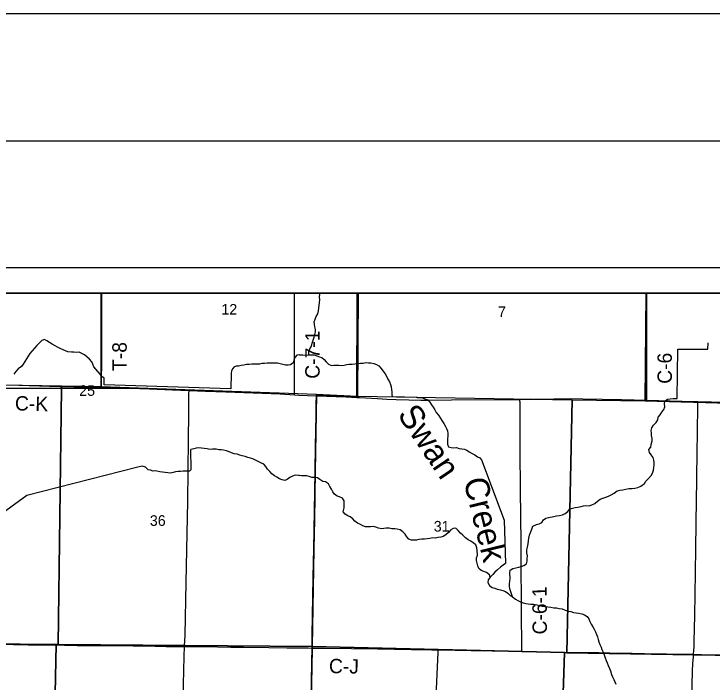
# Model space of a CAD drawing. Extents: x 0 to 42, y 0 to 22.
# Drawn here: x 5.107 to 7.86, y 19.367 to 22 of the extents above; entities that cross this region are included whole.
import ezdxf

# ---------------------------------------------------------------- set-up
doc = ezdxf.new("R2010")
doc.units = 0
for name, color, linetype in [('Default', 7, 'Continuous'), ('GM_X_County_Road', 7, 'Continuous'), ('GM_X_County_Road_Text', 7, 'Continuous'), ('GM_X_Interchange_Ramps', 7, 'Continuous'), ('GM_X_Minor_River', 7, 'Continuous'), ('GM_X_Minor_River_Text', 7, 'Continuous'), ('GM_X_Section', 7, 'Continuous'), ('GM_X_Section_Text', 7, 'Continuous'), ('GM_X_Township_Road', 7, 'Continuous'), ('GM_X_Township_Road_Text', 7, 'Continuous'), ('SH_Border', 7, 'Continuous'), ('SH_Cut_Line', 7, 'Continuous'), ('SH_Data', 7, 'Continuous')]:
    doc.layers.add(name, color=color, linetype=linetype)

msp = doc.modelspace()

# ---------------------------------------------------------------- linework, layer by layer
at = {"layer": 'Default'}
for points in [[(5.4509, 20.9), (4.4477, 20.9), (4.4454, 20.5483), (5.2948, 20.5335), (5.4509, 20.5312)], [(6.4644, 20.9), (5.4509, 20.9), (5.4509, 20.5312), (5.6345, 20.5244), (6.2999, 20.501), (6.462, 20.4934)], [(7.6, 20.9), (6.4644, 20.9), (6.462, 20.4934), (7.3083, 20.4793), (7.5963, 20.4744)], [(8.5893, 20.9), (7.6, 20.9), (7.5963, 20.4744), (8.3092, 20.4559), (8.5911, 20.4514)]]:
    msp.add_lwpolyline(points, close=True, dxfattribs=at)
at = {"layer": 'GM_X_County_Road'}
for points in [[(6.2135, 20.4987), (6.2136, 20.5048), (6.2138, 20.5141), (6.2138, 20.5638), (6.2132, 20.741), (6.2132, 20.7658), (6.2133, 20.8249), (6.2136, 20.9)], [(7.6021, 20.4775), (7.6021, 20.4852), (7.6026, 20.9)], [(5.0427, 20.5382), (5.1257, 20.5362), (5.2872, 20.5311), (5.3432, 20.5304), (5.3991, 20.5296), (5.4507, 20.5283)], [(5.4507, 20.5283), (5.483, 20.5275), (5.5638, 20.5245), (5.6414, 20.5217), (5.7315, 20.5182), (5.7972, 20.5158)], [(5.7796, 19.5062), (5.7797, 19.5073), (5.7821, 19.5508), (5.7866, 19.7591), (5.7903, 19.9519), (5.7924, 20.0793), (5.7935, 20.2006), (5.7951, 20.3219), (5.7962, 20.4245), (5.7971, 20.5022), (5.7972, 20.5158)], [(5.7972, 20.5158), (5.862, 20.5134), (5.9427, 20.51), (6.157, 20.5021), (6.2135, 20.4987)], [(6.2135, 20.4987), (6.2306, 20.4977), (6.3003, 20.4952)], [(6.2825, 19.5006), (6.2829, 19.5488), (6.287, 19.7788), (6.2917, 20.0054), (6.2961, 20.2943), (6.2983, 20.4186), (6.2993, 20.4621), (6.3003, 20.4952)], [(6.3003, 20.4952), (6.417, 20.4902), (6.4593, 20.4883)], [(6.4593, 20.4883), (6.4698, 20.4878), (6.5406, 20.4838), (6.5774, 20.4815), (6.6146, 20.48), (6.6643, 20.4784), (6.711, 20.4777), (6.7452, 20.4777), (6.8322, 20.4787), (7.0903, 20.4805), (7.1023, 20.4807)], [(7.1023, 20.4807), (7.1575, 20.4817), (7.2353, 20.4835), (7.3006, 20.4842), (7.3504, 20.4834), (7.5027, 20.48), (7.6021, 20.4775)], [(7.1102, 19.4873), (7.1101, 19.4976), (7.1088, 19.6466), (7.1087, 19.6682), (7.1088, 19.6736), (7.1071, 19.8343), (7.1066, 19.9152), (7.1048, 20.1238), (7.1037, 20.2794), (7.1033, 20.376), (7.1026, 20.4694), (7.1024, 20.4734), (7.1023, 20.4796), (7.1023, 20.4807)], [(7.6021, 20.4775), (7.6488, 20.4763), (7.7887, 20.4724), (7.8038, 20.472)], [(7.787, 19.4762), (7.7891, 19.5049), (7.79, 19.5267), (7.7917, 19.6294), (7.7942, 19.7973), (7.7956, 19.8938), (7.7985, 20.0866), (7.7997, 20.1581), (7.7997, 20.1706), (7.7999, 20.2017), (7.8006, 20.2421), (7.8012, 20.2763), (7.8019, 20.3447), (7.8037, 20.4629), (7.8038, 20.472)], [(7.8038, 20.472), (7.8571, 20.4705), (7.9317, 20.4681), (7.9752, 20.4667), (8.0436, 20.4648), (8.1741, 20.4605), (8.2425, 20.4581), (8.3077, 20.4565)], [(5.0163, 19.5159), (5.0451, 19.5156), (5.1633, 19.5136), (5.2068, 19.5132), (5.3063, 19.5118), (5.3561, 19.5112), (5.4338, 19.5102), (5.468, 19.51), (5.5768, 19.509), (5.6639, 19.5079), (5.7074, 19.5072), (5.7665, 19.5062), (5.7796, 19.5062)], [(5.7716, 19.1917), (5.7779, 19.4669), (5.7796, 19.5062)], [(5.7796, 19.5062), (5.7976, 19.506), (5.9095, 19.505), (5.9624, 19.5043), (6.0121, 19.5038), (6.1116, 19.5024), (6.1832, 19.5016), (6.2671, 19.5008), (6.2825, 19.5006)], [(6.2634, 18.4929), (6.266, 18.6228), (6.2765, 19.1383), (6.2768, 19.1534), (6.2825, 19.496), (6.2825, 19.5006)], [(6.2825, 19.5006), (6.2917, 19.5006), (6.3352, 19.5003), (6.5404, 19.497), (6.6741, 19.4945), (6.7549, 19.4934), (6.7804, 19.4929)], [(6.7429, 18.4872), (6.7432, 18.4982), (6.7458, 18.5945), (6.7537, 18.8835), (6.7565, 18.983), (6.76, 19.0605), (6.762, 19.1054), (6.7628, 19.1211), (6.7681, 19.2375), (6.7728, 19.34), (6.7796, 19.4828), (6.7799, 19.4859), (6.7804, 19.4929)], [(6.7804, 19.4929), (6.9103, 19.4906), (7.075, 19.4879), (7.1102, 19.4873)], [(7.1102, 19.4873), (7.1621, 19.4865), (7.3299, 19.4836), (7.4139, 19.4824), (7.4574, 19.4815), (7.5444, 19.4803), (7.5941, 19.4795), (7.7682, 19.4765), (7.787, 19.4762)], [(7.7638, 18.7981), (7.7647, 18.8288), (7.7663, 18.8628), (7.767, 18.8942), (7.7675, 18.9147), (7.7681, 18.9395), (7.7708, 19.0266), (7.7744, 19.148), (7.7744, 19.1508), (7.7749, 19.1634), (7.7787, 19.2813), (7.7797, 19.2999), (7.783, 19.4088), (7.7844, 19.4398), (7.7862, 19.4646), (7.787, 19.4762)], [(7.787, 19.4762), (7.8178, 19.4757), (7.9391, 19.4738), (8.1877, 19.4699), (8.2889, 19.4687)]]:
    msp.add_lwpolyline(points, dxfattribs=at)
at = {"layer": 'GM_X_Interchange_Ramps'}
for points in [[(6.2766, 19.154), (6.2823, 19.4965), (6.2823, 19.5012), (6.2827, 19.5494), (6.2868, 19.7794), (6.2915, 20.006), (6.2959, 20.2948), (6.298, 20.4191), (6.299, 20.4627), (6.3001, 20.4958), (6.4167, 20.4908), (6.459, 20.4888), (6.4601, 20.9), (2.1, 20.9)], [(8.9, 18.4589), (8.9, 20.9), (6.4601, 20.9), (6.459, 20.4888), (6.4167, 20.4908), (6.3001, 20.4958), (6.299, 20.4627), (6.298, 20.4191), (6.2959, 20.2948), (6.2915, 20.006), (6.2868, 19.7794), (6.2827, 19.5494), (6.2823, 19.5012), (6.2823, 19.4965), (6.2766, 19.154)]]:
    msp.add_lwpolyline(points, dxfattribs=at)
at = {"layer": 'GM_X_Minor_River'}
for points in [[(6.2694, 20.6563), (6.2696, 20.6696), (6.274, 20.6801), (6.2799, 20.6902), (6.2828, 20.702), (6.2872, 20.7144), (6.2909, 20.7265), (6.2937, 20.7367), (6.2954, 20.7469), (6.296, 20.7564), (6.2932, 20.7667), (6.2915, 20.7773), (6.2913, 20.7868), (6.2946, 20.797), (6.2982, 20.8068), (6.3048, 20.8181), (6.3073, 20.8294), (6.3091, 20.8408), (6.3118, 20.8627), (6.3132, 20.8741), (6.3119, 20.884), (6.3132, 20.895), (6.3128, 20.9)], [(5.4631, 20.5638), (5.453, 20.5708), (5.4464, 20.5805), (5.4294, 20.5998), (5.4213, 20.6095), (5.4178, 20.6194), (5.4138, 20.629), (5.4046, 20.6391), (5.3945, 20.6484), (5.3845, 20.6559), (5.3747, 20.661), (5.3639, 20.6666), (5.3536, 20.666), (5.3434, 20.6667), (5.3331, 20.6665), (5.3199, 20.6687), (5.3101, 20.6716), (5.3004, 20.6764), (5.2895, 20.6819), (5.279, 20.6871), (5.2689, 20.6922), (5.2576, 20.6978), (5.2468, 20.7049), (5.2367, 20.7119), (5.2266, 20.7167), (5.217, 20.7124), (5.2069, 20.7039), (5.1976, 20.6935), (5.1882, 20.6823), (5.1784, 20.6715), (5.1691, 20.6611), (5.1624, 20.6513), (5.1557, 20.6405), (5.1494, 20.6304), (5.1431, 20.6199), (5.136, 20.6098), (5.124, 20.6006), (5.1147, 20.5905), (5.1065, 20.5801)], [(7.723, 20.4842), (7.725, 20.6786), (7.8428, 20.6781), (7.8448, 20.7031)], [(6.2332, 20.6559), (6.223, 20.6549), (6.2148, 20.6453), (6.2111, 20.6355), (6.2075, 20.6245), (6.1978, 20.6175), (6.1883, 20.6159), (6.178, 20.6157), (6.1675, 20.6182), (6.1565, 20.6215), (6.1467, 20.6229), (6.1365, 20.6235), (6.1259, 20.6233), (6.1058, 20.6238), (6.0947, 20.6225), (6.0845, 20.6216), (6.0745, 20.6195), (6.0651, 20.6198), (6.0556, 20.6196), (6.0449, 20.6191), (6.0339, 20.6186), (6.024, 20.6176), (6.0134, 20.6156), (6.0023, 20.614), (5.9928, 20.6119), (5.9829, 20.6113), (5.9733, 20.6081), (5.9662, 20.5975), (5.9646, 20.5924), (5.9633, 20.5845)], [(6.2332, 20.6559), (6.2464, 20.6561), (6.2599, 20.6553), (6.2694, 20.6563), (6.2803, 20.6557), (6.291, 20.6562), (6.3011, 20.653), (6.3113, 20.6486), (6.3211, 20.6457), (6.3307, 20.638), (6.3381, 20.6283), (6.3478, 20.6198), (6.3587, 20.6146), (6.3689, 20.6152), (6.3788, 20.6157), (6.3886, 20.6155), (6.3985, 20.6149), (6.4087, 20.6151), (6.4194, 20.6176), (6.4293, 20.62), (6.4406, 20.6202), (6.4516, 20.6211), (6.4619, 20.622), (6.4737, 20.6233), (6.4835, 20.6239), (6.4942, 20.6255), (6.5044, 20.6246), (6.5146, 20.6248), (6.5255, 20.6226), (6.5361, 20.6179), (6.5462, 20.6131), (6.5551, 20.6031), (6.5613, 20.5927), (6.5702, 20.5819), (6.5757, 20.5719), (6.5819, 20.5604), (6.5877, 20.5504), (6.5917, 20.54), (6.5938, 20.5298), (6.5958, 20.5198), (6.5968, 20.5099), (6.5969, 20.5004), (6.5983, 20.4909), (6.5979, 20.4917)], [(5.9633, 20.5845), (5.9622, 20.5226), (5.4629, 20.538), (5.4631, 20.5638)], [(6.6975, 20.4878), (6.5983, 20.4909)], [(6.6975, 20.4878), (6.7073, 20.4876), (6.7175, 20.4866), (6.7277, 20.4834), (6.7386, 20.479), (6.7471, 20.4693), (6.7533, 20.4597), (6.76, 20.4497), (6.767, 20.4397), (6.7724, 20.4289), (6.7817, 20.4185), (6.7883, 20.4077), (6.7945, 20.3977), (6.8026, 20.3862), (6.807, 20.3766), (6.8125, 20.3662), (6.8164, 20.3567), (6.8181, 20.3464), (6.8179, 20.3354), (6.8169, 20.3248), (6.8167, 20.3153), (6.8169, 20.3043), (6.8201, 20.2943), (6.8306, 20.2907), (6.8408, 20.2897), (6.8519, 20.2914), (6.8628, 20.2874), (6.873, 20.2857), (6.8832, 20.2843), (6.8929, 20.2807), (6.9026, 20.274), (6.9139, 20.2677), (6.9244, 20.2622), (6.9348, 20.2537), (6.9446, 20.25), (6.9513, 20.2423)], [(7.0733, 19.7022), (7.0629, 19.7335), (7.0613, 19.7442), (7.0615, 19.7541), (7.0628, 19.7643), (7.0638, 19.7749), (7.062, 19.797), (7.0641, 19.8072), (7.0748, 19.8142), (7.0866, 19.8166), (7.098, 19.819), (7.1076, 19.8222), (7.1179, 19.8262), (7.1275, 19.8328), (7.1307, 19.8427), (7.1309, 19.854), (7.1315, 19.8643), (7.1295, 19.8761), (7.1293, 19.8875), (7.1318, 19.8988), (7.1347, 19.9113), (7.1365, 19.9227), (7.1371, 19.934), (7.1404, 19.9457), (7.1444, 19.9555), (7.1492, 19.9695), (7.1532, 19.9808), (7.167, 19.987), (7.178, 19.9902), (7.1883, 19.9949), (7.1946, 20.0054), (7.2046, 20.0124), (7.2153, 20.0152), (7.2366, 20.0186), (7.2468, 20.0214), (7.2582, 20.0231), (7.27, 20.0255), (7.2808, 20.031), (7.2908, 20.0392), (7.2989, 20.0489), (7.31, 20.0521), (7.3199, 20.0541), (7.3301, 20.0558), (7.3431, 20.0582), (7.3526, 20.0607), (7.3625, 20.0624), (7.3757, 20.0614), (7.386, 20.065), (7.3971, 20.0708), (7.4075, 20.079), (7.4183, 20.0871), (7.4294, 20.0918), (7.4416, 20.0954), (7.4515, 20.0993), (7.4626, 20.1044), (7.4737, 20.1114), (7.486, 20.1199), (7.4959, 20.1224), (7.5081, 20.124), (7.5195, 20.1272), (7.532, 20.1292), (7.5449, 20.129), (7.5556, 20.131), (7.5673, 20.1331), (7.5792, 20.1389), (7.593, 20.1485), (7.5985, 20.1583), (7.6094, 20.169), (7.6202, 20.1802), (7.6253, 20.19), (7.6293, 20.2021), (7.6299, 20.2119), (7.6317, 20.2225), (7.6319, 20.232), (7.6298, 20.2415), (7.6277, 20.2518), (7.62, 20.2619), (7.6126, 20.2719), (7.6105, 20.2826), (7.6183, 20.2927), (7.6196, 20.3025), (7.6233, 20.3169), (7.6239, 20.3267), (7.6211, 20.3378), (7.6213, 20.3473), (7.6196, 20.3576), (7.6225, 20.3685), (7.6291, 20.3786), (7.64, 20.389), (7.6459, 20.4003), (7.648, 20.4105), (7.655, 20.4203), (7.6624, 20.4304), (7.6698, 20.4408), (7.6731, 20.4518), (7.6722, 20.4636), (7.6739, 20.4738), (7.6846, 20.4816), (7.6953, 20.4829), (7.7063, 20.4838), (7.7158, 20.4843)], [(7.7158, 20.4843), (7.723, 20.4842)], [(6.2285, 20.1811), (6.2156, 20.1818), (6.2056, 20.1774), (6.1945, 20.1731), (6.1845, 20.165), (6.1749, 20.161), (6.1639, 20.1639), (6.1538, 20.1676), (6.1437, 20.1739), (6.134, 20.1794), (6.1239, 20.1868), (6.1165, 20.1965), (6.1073, 20.2062), (6.0995, 20.2159), (6.0925, 20.2255), (6.0828, 20.2291), (6.073, 20.2351), (6.0622, 20.2402), (6.049, 20.2462), (6.0392, 20.2491), (6.029, 20.252), (6.0181, 20.2553), (6.0068, 20.2586), (5.997, 20.2614), (5.9865, 20.2647), (5.9759, 20.2661), (5.965, 20.2705), (5.9552, 20.2741), (5.9454, 20.2774), (5.9337, 20.2807), (5.9239, 20.2824), (5.9144, 20.2823), (5.9046, 20.284), (5.8898, 20.2847), (5.8788, 20.2834), (5.8682, 20.2859), (5.8572, 20.2873), (5.8459, 20.2887), (5.8357, 20.2893), (5.8258, 20.288), (5.8162, 20.2856), (5.8059, 20.2837), (5.8044, 20.2832)], [(5.8063, 20.2046), (5.8044, 20.2832)], [(6.9513, 20.2423), (7.0404, 20.0043), (7.0453, 19.8341)], [(5.5906, 20.2124), (5.157, 20.1018)], [(5.8063, 20.2046), (5.7997, 20.1978), (5.7846, 20.1979), (5.7736, 20.1977), (5.7637, 20.1968), (5.7542, 20.197), (5.7439, 20.1953), (5.7343, 20.1921), (5.7248, 20.1905), (5.7142, 20.1907), (5.7029, 20.1929), (5.693, 20.1935), (5.6821, 20.1948), (5.6651, 20.1986), (5.6556, 20.1981), (5.6454, 20.2013), (5.6356, 20.2035), (5.6252, 20.2134), (5.6125, 20.2174), (5.5906, 20.2124)], [(6.9855, 19.7799), (6.9819, 19.7887), (6.9707, 19.798), (6.9594, 19.8021), (6.9496, 19.8064), (6.9399, 19.8146), (6.9364, 19.8249), (6.9315, 19.8455), (6.9313, 19.8565), (6.9346, 19.8664), (6.9342, 19.8861), (6.9329, 19.8956), (6.9282, 19.9071), (6.9181, 19.9149), (6.9084, 19.9219), (6.8986, 19.9267), (6.8882, 19.9353), (6.8774, 19.9461), (6.8677, 19.9535), (6.8585, 19.9636), (6.8488, 19.9725), (6.8389, 19.9719), (6.8294, 19.9668), (6.8204, 19.9556), (6.8096, 19.9467), (6.8001, 19.9408), (6.7901, 19.9376), (6.7787, 19.9359), (6.7689, 19.9342), (6.7579, 19.9345), (6.7472, 19.9328), (6.7366, 19.9307), (6.7263, 19.9298), (6.715, 19.9296), (6.704, 19.9287), (6.6941, 19.9263), (6.6846, 19.9253), (6.6747, 19.9255), (6.6642, 19.9291), (6.6564, 19.9388), (6.6494, 19.9492), (6.6402, 19.9589), (6.6297, 19.9659), (6.6184, 19.9696), (6.6086, 19.9705), (6.5972, 19.9711), (6.5859, 19.9725), (6.5753, 19.9731), (6.5654, 19.9721), (6.5559, 19.9708), (6.545, 19.9726), (6.5341, 19.9766), (6.5231, 19.9791), (6.5125, 19.9785), (6.5027, 19.9783), (6.4928, 19.9785), (6.4827, 19.9829), (6.4729, 19.9869), (6.462, 19.9932), (6.4512, 20.0006), (6.4427, 20.0103), (6.433, 20.0173), (6.4232, 20.0217), (6.4127, 20.028), (6.4046, 20.0377), (6.4087, 20.0528), (6.4089, 20.0622), (6.4095, 20.0717), (6.4089, 20.0812), (6.4023, 20.0912), (6.391, 20.096), (6.3812, 20.0996), (6.3704, 20.1067), (6.3649, 20.1163), (6.359, 20.1267), (6.352, 20.1371), (6.3473, 20.1478), (6.3358, 20.156), (6.3248, 20.1574), (6.3136, 20.1652), (6.3039, 20.1714), (6.2941, 20.1732), (6.2819, 20.1734), (6.2714, 20.1767), (6.2616, 20.1788), (6.2506, 20.179), (6.2408, 20.1796), (6.2322, 20.1803), (6.2285, 20.1811)], [(5.157, 20.1018), (5.0296, 20.0101), (4.9062, 20.0053), (4.8997, 20.0013), (4.898, 19.9934), (4.8961, 19.9801), (4.8937, 19.9745), (4.8853, 19.9712), (4.8412, 19.9665)], [(7.0453, 19.8341), (7.0357, 19.8275), (7.0253, 19.819), (7.0141, 19.8082), (7.0037, 19.8), (6.9959, 19.7899), (6.9855, 19.7799), (6.9769, 19.7694), (6.9763, 19.7592), (6.9818, 19.7477), (6.993, 19.7395), (7.0031, 19.7362), (7.0129, 19.733), (7.025, 19.7305), (7.0352, 19.728), (7.0449, 19.7236), (7.055, 19.717), (7.0636, 19.7073), (7.0733, 19.7022), (7.0845, 19.6932), (7.0942, 19.6877), (7.1051, 19.6822), (7.1152, 19.6782), (7.1251, 19.6761), (7.1349, 19.6751), (7.1451, 19.673), (7.1564, 19.6732), (7.1685, 19.6706), (7.1787, 19.6682), (7.1904, 19.666), (7.201, 19.6643), (7.2127, 19.6625), (7.2244, 19.6612), (7.2353, 19.6587), (7.2463, 19.6592), (7.2572, 19.6559), (7.2686, 19.6546), (7.281, 19.6501), (7.2927, 19.6465), (7.3025, 19.644), (7.313, 19.6411), (7.3243, 19.6394), (7.3342, 19.6377), (7.3462, 19.6352), (7.3564, 19.6315), (7.3669, 19.6253), (7.3739, 19.6156), (7.3775, 19.6049), (7.3829, 19.5953), (7.3892, 19.5846), (7.395, 19.5749), (7.3998, 19.565), (7.4037, 19.5539), (7.4084, 19.5443), (7.4105, 19.534), (7.4137, 19.5244), (7.4177, 19.5141), (7.4228, 19.5038), (7.4256, 19.4942), (7.4303, 19.4839), (7.4339, 19.4732), (7.4386, 19.4624), (7.4429, 19.4513), (7.4461, 19.4418), (7.4508, 19.4314), (7.4559, 19.4199), (7.4588, 19.4104), (7.4634, 19.3966), (7.4674, 19.3867), (7.4721, 19.3771), (7.4761, 19.3675), (7.4804, 19.3579)]]:
    msp.add_lwpolyline(points, dxfattribs=at)
at = {"layer": 'GM_X_Section'}
for points in [[(4.2909, 20.5517), (4.4454, 20.5483), (5.2948, 20.5335), (5.2947, 20.5242), (4.2905, 20.5288)], [(4.2905, 20.5288), (5.2947, 20.5242), (5.2809, 19.5139), (5.2739, 19.514), (4.2741, 19.5242)], [(5.2947, 20.5242), (5.6345, 20.5244), (6.2999, 20.501), (6.2834, 19.5071), (5.2809, 19.5139)], [(5.2948, 20.5335), (5.4509, 20.5312), (5.6345, 20.5244), (5.2947, 20.5242)], [(6.2999, 20.501), (6.462, 20.4934), (7.3083, 20.4793), (7.2872, 19.4822), (7.2774, 19.4824), (6.2834, 19.5071)], [(7.3083, 20.4793), (7.5963, 20.4744), (8.3092, 20.4559), (8.3071, 19.914), (8.2893, 19.4656), (7.2872, 19.4822)], [(5.2524, 18.4847), (4.2501, 18.4923), (4.2741, 19.5242), (5.2739, 19.514)], [(5.2809, 19.5139), (6.2834, 19.5071), (6.2631, 18.4885), (5.2524, 18.4847), (5.2739, 19.514)], [(6.2834, 19.5071), (7.2774, 19.4824), (7.2453, 18.4817), (6.2631, 18.4885)], [(7.2774, 19.4824), (7.2872, 19.4822), (8.2893, 19.4656), (8.2652, 18.4704), (7.2453, 18.4817)]]:
    msp.add_lwpolyline(points, close=True, dxfattribs=at)
at = {"layer": 'GM_X_Township_Road'}
for points in [[(5.4507, 20.5283), (5.4509, 20.5359), (5.4527, 20.6105), (5.4528, 20.6447), (5.4527, 20.9)], [(5.0163, 19.5159), (5.0451, 19.5156), (5.1633, 19.5136), (5.2068, 19.5132), (5.3063, 19.5118), (5.3561, 19.5112), (5.4338, 19.5102), (5.468, 19.51), (5.5768, 19.509), (5.6639, 19.5079), (5.7074, 19.5072), (5.7665, 19.5062), (5.7796, 19.5062)], [(5.7796, 19.5062), (5.7976, 19.506), (5.9095, 19.505), (5.9624, 19.5043), (6.0121, 19.5038), (6.1116, 19.5024), (6.1832, 19.5016), (6.2671, 19.5008), (6.2825, 19.5006)], [(6.2825, 19.5006), (6.2917, 19.5006), (6.3352, 19.5003), (6.5404, 19.497), (6.6741, 19.4945), (6.7549, 19.4934), (6.7804, 19.4929)], [(6.7804, 19.4929), (6.9103, 19.4906), (7.075, 19.4879), (7.1102, 19.4873)], [(7.1102, 19.4873), (7.1621, 19.4865), (7.3299, 19.4836), (7.4139, 19.4824), (7.4574, 19.4815), (7.5444, 19.4803), (7.5941, 19.4795), (7.7682, 19.4765), (7.787, 19.4762)], [(7.787, 19.4762), (7.8178, 19.4757), (7.9391, 19.4738), (8.1877, 19.4699), (8.2889, 19.4687)]]:
    msp.add_lwpolyline(points, dxfattribs=at)
at = {"layer": 'SH_Border'}
msp.add_lwpolyline([(1.5, 21.5), (33.5, 21.5), (33.5, 0.5), (1.5, 0.5)], close=True, dxfattribs=at)
at = {"layer": 'SH_Cut_Line'}
msp.add_lwpolyline([(0, 0), (34, 0), (34, 22), (0, 22)], close=True, dxfattribs=at)
at = {"layer": 'SH_Data'}
for p, q in [((2, 21), (9, 21)), ((2.1, 20.9), (8.9, 20.9))]:
    msp.add_line(p, q, dxfattribs=at)

# ---------------------------------------------------------------- texts
at = {"layer": 'GM_X_County_Road_Text'}
for s, rotation, p in [('C-7-1', 90, (6.3124, 20.562)), ('C-6', 90, (7.7016, 20.542)), ('C-K', 358.4097, (5.1101, 20.4375)), ('C-6-1', 90.5851, (7.2091, 19.5542)), ('C-J', 359.0128, (6.3487, 19.4016))]:
    msp.add_text(s, height=0.05682, rotation=rotation, dxfattribs=at).set_placement(p)
at = {"layer": 'GM_X_Minor_River_Text'}
for s, rotation, p in [('Swan', 303.9533, (6.6165, 20.4208)), ('Creek', 283.7207, (6.8789, 20.1617))]:
    msp.add_text(s, height=0.09476, rotation=rotation, dxfattribs=at).set_placement(p)
at = {"layer": 'GM_X_Section_Text'}
for s, height, p in [('12', 0.04186, (5.9249, 20.8149)), ('7', 0.0419, (7.0158, 20.8051)), ('25', 0.04186, (5.3641, 20.4946)), ('36', 0.04186, (5.6429, 19.9821)), ('31', 0.04186, (6.7624, 19.9596))]:
    msp.add_text(s, height=height, rotation=0, dxfattribs=at).set_placement(p)
at = {"layer": 'GM_X_Township_Road_Text'}
msp.add_text('T-8', height=0.05682, rotation=90, dxfattribs=at).set_placement((5.5515, 20.5928))

doc.saveas('drawing.dxf')
